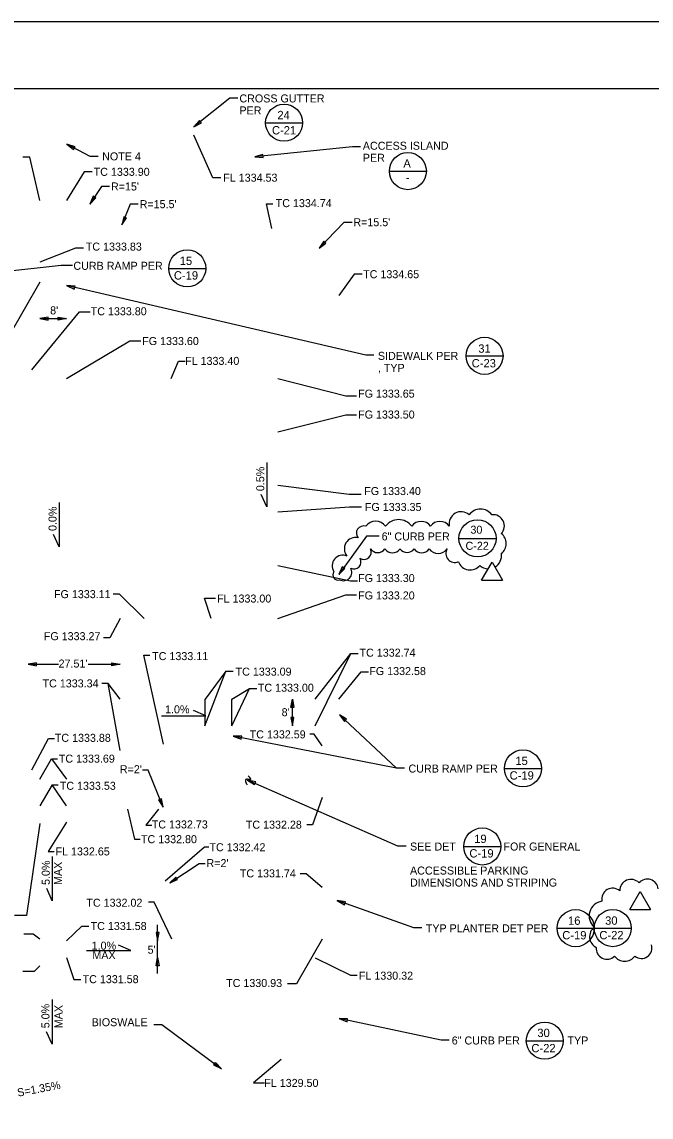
# Model space of a CAD drawing. Extents: x 0 to 3.5, y 0 to 3.39.
# Drawn here: x 1.981 to 2.766, y 1.132 to 2.5 of the extents above; entities that cross this region are included whole.
import ezdxf

# ---------------------------------------------------------------- set-up
doc = ezdxf.new("R2010")
doc.units = 0
for name, color, linetype in [('C-MARK', 7, 'Continuous'), ('C-MATC', 7, 'Continuous'), ('C-REVC', 7, 'Continuous'), ('C-TEXT', 7, 'Continuous'), ('G-TTLB-OTLN', 7, 'Continuous'), ('G-TTLB-VIEW', 7, 'Continuous')]:
    doc.layers.add(name, color=color, linetype=linetype)

msp = doc.modelspace()

# ---------------------------------------------------------------- linework, layer by layer
at = {"layer": 'C-MARK'}
for p, q in [((2.0031, 2.1293), (2.0364, 2.1293)), ((2.2863, 1.9495), (2.2863, 1.8941)), ((2.2863, 1.8941), (2.2794, 1.9095)), ((2.027, 1.8998), (2.027, 1.8444)), ((2.027, 1.8444), (2.0201, 1.8598)), ((1.9885, 1.6976), (2.0264, 1.6976)), ((2.0635, 1.6976), (2.1031, 1.6976)), ((2.2353, 1.6887), (2.2093, 1.654)), ((2.2427, 1.654), (2.2647, 1.6673)), ((2.2093, 1.6207), (2.2093, 1.654)), ((2.2427, 1.6207), (2.2427, 1.654)), ((2.3182, 1.6207), (2.3182, 1.654)), ((2.1547, 1.6329), (2.2101, 1.6329)), ((2.2101, 1.6329), (2.1947, 1.6398)), ((2.0175, 1.5793), (2.0364, 1.554)), ((2.0182, 1.5469), (2.0031, 1.5207)), ((2.0185, 1.4575), (2.0185, 1.4021)), ((2.0185, 1.4021), (2.0116, 1.4175)), ((2.1499, 1.352), (2.1499, 1.372)), ((1.9948, 1.3605), (1.9832, 1.3605)), ((2.0031, 1.354), (1.9948, 1.3605)), ((2.1166, 1.3399), (2.1012, 1.3467)), ((2.1499, 1.3311), (2.1499, 1.352)), ((2.0612, 1.3399), (2.1166, 1.3399)), ((2.1499, 1.3111), (2.1499, 1.3311)), ((1.9961, 1.3138), (1.9818, 1.3138)), ((2.0031, 1.3207), (1.9961, 1.3138)), ((2.0182, 1.2785), (2.0182, 1.2231)), ((2.0182, 1.2231), (2.0113, 1.2385))]:
    msp.add_line(p, q, dxfattribs=at)
for points in [[(2.2501, 2.4046), (2.2401, 2.4046), (2.1953, 2.3688)], [(2.2288, 2.305), (2.2188, 2.305), (2.1953, 2.3583)], [(2.0758, 2.332), (2.0658, 2.332), (2.0368, 2.3471)], [(2.4031, 2.3441), (2.3931, 2.3441), (2.2713, 2.3313)], [(2.0031, 2.277), (1.9907, 2.3312), (1.9819, 2.3312)], [(2.0682, 2.3128), (2.0582, 2.3128), (2.0364, 2.277)], [(2.0898, 2.2942), (2.0798, 2.2942), (2.0654, 2.2725)], [(2.1258, 2.2721), (2.1158, 2.2721), (2.1055, 2.2463)], [(2.2927, 2.2417), (2.2857, 2.2728), (2.2938, 2.2728)], [(2.3926, 2.2494), (2.3826, 2.2494), (2.3516, 2.2173)], [(2.0574, 2.2172), (2.0474, 2.2172), (2.0031, 2.2)], [(2.0439, 2.1956), (2.0296, 2.1956), (1.9542, 2.1875)], [(2.4051, 2.1847), (2.3951, 2.1847), (2.376, 2.1583)], [(2.0031, 2.175), (1.964, 2.1066), (1.955, 2.1066)], [(2.42, 2.0835), (2.41, 2.0835), (2.0364, 2.1707)], [(1.993, 2.0653), (2.0525, 2.1379), (2.066, 2.1379)], [(2.0364, 2.0545), (2.1155, 2.1014), (2.129, 2.1014)], [(2.1668, 2.0545), (2.1762, 2.0763), (2.1845, 2.0763)], [(2.3001, 2.0545), (2.3847, 2.0327), (2.3982, 2.0327)], [(2.3001, 1.9878), (2.3847, 2.0091), (2.3982, 2.0091)], [(2.3001, 1.9211), (2.3891, 1.9101), (2.4039, 1.9101)], [(2.3001, 1.8878), (2.3896, 1.8942), (2.4043, 1.8942)], [(2.4265, 1.8574), (2.4105, 1.8575), (2.376, 1.8097)], [(2.3001, 1.8211), (2.3907, 1.8019), (2.3994, 1.8019)], [(2.1332, 1.7547), (2.1023, 1.7849), (2.0947, 1.7849)], [(2.2168, 1.7545), (2.2087, 1.7802), (2.2222, 1.7802)], [(2.3001, 1.7545), (2.3847, 1.7841), (2.3982, 1.7841)], [(2.1031, 1.7545), (2.0902, 1.7305), (2.0826, 1.7305)], [(2.3468, 1.6207), (2.3912, 1.7111), (2.4003, 1.7111)], [(2.3468, 1.654), (2.3912, 1.7111), (2.4003, 1.7111)], [(2.1572, 1.5978), (2.1327, 1.709), (2.1402, 1.709)], [(2.2091, 1.6207), (2.2353, 1.6887), (2.2444, 1.6887)], [(2.376, 1.654), (2.4039, 1.6881), (2.4131, 1.6881)], [(2.1031, 1.5899), (2.0881, 1.6735), (2.0805, 1.6735)], [(2.1031, 1.654), (2.0881, 1.6735), (2.0805, 1.6735)], [(2.2427, 1.6207), (2.2647, 1.6673), (2.2738, 1.6673)], [(2.4582, 1.5679), (2.4482, 1.5679), (2.3771, 1.6345)], [(1.993, 1.5656), (2.0139, 1.6046), (2.0215, 1.6046)], [(2.4582, 1.5679), (2.4482, 1.5679), (2.2445, 1.6078)], [(2.3552, 1.5957), (2.3455, 1.6101), (2.3398, 1.6101)], [(2.0031, 1.554), (2.0175, 1.5793), (2.025, 1.5793)], [(2.1569, 1.519), (2.1384, 1.5654), (2.1312, 1.5654)], [(2.0364, 1.5207), (2.0182, 1.5469), (2.0258, 1.5469)], [(2.46, 1.4704), (2.45, 1.4704), (2.2621, 1.5529)], [(2.3552, 1.5311), (2.3435, 1.4969), (2.3364, 1.4969)], [(2.1124, 1.5165), (2.1212, 1.4792), (2.1284, 1.4792)], [(2.151, 1.5165), (2.1355, 1.4966), (2.1426, 1.4966)], [(2.0032, 1.4987), (1.9862, 1.3836), (1.9714, 1.3836)], [(2.0364, 1.5002), (2.0133, 1.4634), (2.0209, 1.4634)], [(2.1593, 1.4268), (2.2086, 1.4695), (2.214, 1.4695)], [(2.1652, 1.4244), (2.202, 1.4488), (2.2092, 1.4488)], [(2.3552, 1.4187), (2.3352, 1.4358), (2.328, 1.4358)], [(2.1677, 1.354), (2.1458, 1.4004), (2.1386, 1.4004)], [(2.4798, 1.3683), (2.4698, 1.3683), (2.3739, 1.4023)], [(2.0364, 1.352), (2.0556, 1.3705), (2.064, 1.3705)], [(2.3552, 1.354), (2.3233, 1.2983), (2.3121, 1.2983)], [(2.0364, 1.3311), (2.0455, 1.3038), (2.054, 1.3038)], [(2.3467, 1.3307), (2.3907, 1.309), (2.3992, 1.309)], [(2.1453, 1.2476), (2.1553, 1.2476), (2.2298, 1.1922)], [(2.5138, 1.2277), (2.5038, 1.2277), (2.3765, 1.2548)], [(2.3041, 1.2039), (2.2697, 1.1747), (2.2833, 1.1747)]]:
    msp.add_lwpolyline(points, dxfattribs=at)
msp.add_open_spline([(2.263, 1.558), (2.2689, 1.5523), (2.2569, 1.555), (2.2617, 1.5469)], degree=2, dxfattribs=at)
at = {"layer": 'C-MATC'}
msp.add_line((0.6372, 2.4167), (2.713, 2.4167), dxfattribs=at)
at = {"layer": 'C-REVC'}
for centre, radius, start, end in [((2.553, 1.8736), 0.0178, 36.8699, 143.1301), ((2.4222, 1.8608), 0.0154, 36.8699, 143.1301), ((2.4508, 1.8578), 0.0204, 36.8699, 143.1301), ((2.4789, 1.8613), 0.0147, 36.8699, 143.1301), ((2.5023, 1.8613), 0.0147, 36.8699, 143.1301), ((2.5288, 1.873), 0.0151, 48.7253, 191.1819), ((2.5688, 1.8704), 0.014, 316.581, 96.5491), ((2.4073, 1.8612), 0.00921, 74.4697, 218.909), ((2.5695, 1.8483), 0.0157, 306.8699, 53.1301), ((2.397, 1.8418), 0.014, 76.8763, 220.2645), ((2.3811, 1.8205), 0.0133, 66.89, 213.7391), ((2.4075, 1.8376), 0.00911, 238.444, 25.7343), ((2.4247, 1.8483), 0.0113, 216.8699, 323.1301), ((2.4431, 1.8486), 0.0118, 216.8699, 323.1301), ((2.4613, 1.8482), 0.011, 216.8699, 323.1301), ((2.4795, 1.8486), 0.0118, 216.8699, 323.1301), ((2.5002, 1.8501), 0.0141, 216.8699, 323.1301), ((2.5208, 1.8357), 0.011, 147.4131, 294.5304), ((2.563, 1.8331), 0.0162, 300.2363, 9.4597), ((2.3951, 1.8255), 0.00879, 242.2766, 29.7336), ((2.5401, 1.8309), 0.0156, 199.7229, 320.7723), ((2.563, 1.8331), 0.0162, 227.8866, 267.9338), ((2.3751, 1.8092), 0.00645, 142.6171, 288.0053), ((2.3819, 1.8124), 0.0105, 242.9766, 30.3928), ((2.7408, 1.4148), 0.014, 44.4945, 181.1728), ((2.7611, 1.4153), 0.0138, 6.9456, 138.0032), ((2.7179, 1.4042), 0.0136, 48.9741, 191.6731), ((2.7072, 1.383), 0.0187, 98.3653, 228.3728), ((2.7041, 1.3572), 0.015, 128.1326, 243.2886), ((2.7108, 1.3425), 0.0135, 174.6579, 313.9222), ((2.7538, 1.3432), 0.0132, 232.1847, 17.3271), ((2.7329, 1.3425), 0.016, 216.8699, 323.1301)]:
    msp.add_arc(centre, radius, start, end, dxfattribs=at)
at = {"layer": 'C-TEXT'}
for p, q in [((2.2846, 2.3739), (2.3309, 2.3739)), ((2.439, 2.3136), (2.4853, 2.3136)), ((2.1637, 2.192), (2.21, 2.192)), ((2.5347, 2.0827), (2.581, 2.0827)), ((2.526, 1.8548), (2.5724, 1.8548)), ((2.5544, 1.8026), (2.5675, 1.8252)), ((2.5675, 1.8252), (2.5805, 1.8026)), ((2.5544, 1.8026), (2.5805, 1.8026)), ((2.5544, 1.8026), (2.5544, 1.8026)), ((2.5805, 1.8026), (2.5805, 1.8026)), ((2.5827, 1.5673), (2.629, 1.5673)), ((2.5319, 1.4698), (2.5782, 1.4698)), ((2.7392, 1.391), (2.7523, 1.4136)), ((2.7523, 1.4136), (2.7653, 1.391)), ((2.7392, 1.391), (2.7653, 1.391)), ((2.7392, 1.391), (2.7392, 1.391)), ((2.7653, 1.391), (2.7653, 1.391)), ((2.6484, 1.3677), (2.6947, 1.3677)), ((2.6947, 1.3678), (2.741, 1.3678)), ((2.6099, 1.2271), (2.6562, 1.2271))]:
    msp.add_line(p, q, dxfattribs=at)
for points in [[(2.2023, 2.3767), (2.1953, 2.3688), (2.2046, 2.3738)], [(2.0469, 2.3439), (2.0368, 2.3471), (2.0452, 2.3406)], [(2.2815, 2.3342), (2.2713, 2.3313), (2.2818, 2.3305)], [(2.0696, 2.2822), (2.0654, 2.2725), (2.0727, 2.2801)], [(2.1077, 2.2566), (2.1055, 2.2463), (2.1111, 2.2553)], [(2.3575, 2.226), (2.3516, 2.2173), (2.3601, 2.2235)], [(2.0469, 2.1697), (2.0364, 2.1707), (2.046, 2.1662)], [(2.0135, 2.1311), (2.0031, 2.1293), (2.0135, 2.1275)], [(2.026, 2.1311), (2.0364, 2.1293), (2.026, 2.1275)], [(2.3805, 1.8194), (2.376, 1.8098), (2.3835, 1.8173)], [(1.9989, 1.6994), (1.9885, 1.6976), (1.9989, 1.6957)], [(2.0927, 1.6994), (2.1031, 1.6976), (2.0927, 1.6957)], [(2.3164, 1.6436), (2.3182, 1.654), (2.3201, 1.6436)], [(2.3164, 1.6311), (2.3182, 1.6207), (2.3201, 1.6311)], [(2.3859, 1.6288), (2.3771, 1.6345), (2.3834, 1.6261)], [(2.255, 1.6076), (2.2445, 1.6078), (2.2543, 1.604)], [(2.2725, 1.5506), (2.2621, 1.5529), (2.271, 1.5473)], [(2.1513, 1.528), (2.1569, 1.519), (2.1547, 1.5293)], [(2.1729, 1.4317), (2.1652, 1.4244), (2.1749, 1.4286)], [(2.3843, 1.4006), (2.3739, 1.4023), (2.3831, 1.3971)], [(2.1481, 1.3624), (2.1499, 1.352), (2.1518, 1.3624)], [(2.1481, 1.3207), (2.1499, 1.3311), (2.1518, 1.3207)], [(2.3871, 1.2545), (2.3765, 1.2548), (2.3864, 1.2509)], [(2.2224, 1.1998), (2.2298, 1.1922), (2.2202, 1.1968)]]:
    msp.add_lwpolyline(points, close=True, dxfattribs=at)
msp.add_circle((2.5492, 1.8548), 0.0232, dxfattribs=at)
for centre in [(2.3078, 2.374), (2.4623, 2.3136), (2.187, 2.1921), (2.558, 2.0828), (2.606, 1.5674), (2.5552, 1.4699), (2.6717, 1.3678), (2.718, 1.3679), (2.6332, 1.2272)]:
    msp.add_ellipse(centre, major_axis=(0, 0.0232), ratio=0.994695, dxfattribs=at)
at = {"layer": 'G-TTLB-OTLN'}
msp.add_lwpolyline([(0, 0), (3.5, 0), (3.5, 2.5), (0, 2.5)], close=True, dxfattribs=at)
at = {"layer": 'G-TTLB-VIEW'}
msp.add_lwpolyline([(0.1667, 2.4167), (3.0729, 2.4167), (3.0729, 0.0833), (0.1667, 0.0833)], close=True, dxfattribs=at)

# ---------------------------------------------------------------- texts
at = {"layer": 'C-TEXT'}
for s, height, rotation, p in [('CROSS GUTTER', 0.01, 360, (2.2521, 2.3994)), ('PER', 0.01, 360, (2.2521, 2.3844)), ('24', 0.01042, 360, (2.2995, 2.3784)), ('C-21', 0.01042, 360, (2.2927, 2.3594)), ('ACCESS ISLAND', 0.01, 360, (2.4061, 2.3403)), ('PER', 0.01, 360, (2.4061, 2.3253)), ('A', 0.0104, 360, (2.4567, 2.318)), ('-', 0.0104, 360, (2.4597, 2.3004)), ('15', 0.01042, 360, (2.1776, 2.1963)), ('CURB RAMP PER', 0.01, 360, (2.0449, 2.1903)), ('C-19', 0.01042, 360, (2.1703, 2.1781)), ('31', 0.01042, 360, (2.5502, 2.0867)), ('SIDEWALK PER', 0.01, 360, (2.4249, 2.0778)), (', TYP', 0.01, 360, (2.4249, 2.0628)), ('C-23', 0.01042, 360, (2.542, 2.0684)), ('0.5%', 0.01, 90, (2.2831, 1.9138)), ('0.0%', 0.01, 90, (2.0239, 1.864)), ('15', 0.01042, 360, (2.5965, 1.5716)), ('CURB RAMP PER', 0.01, 360, (2.4631, 1.5622)), ('C-19', 0.01042, 360, (2.5893, 1.5534)), ('19', 0.01042, 360, (2.5451, 1.4742)), ('SEE DET                FOR GENERAL', 0.01, 360, (2.465, 1.4648)), ('C-19', 0.01042, 360, (2.5391, 1.4561)), ('5.0%', 0.01, 90, (2.0154, 1.4218)), ('MAX', 0.01, 90, (2.0307, 1.4218)), ('ACCESSIBLE PARKING', 0.01, 360, (2.465, 1.4348)), ('DIMENSIONS AND STRIPING', 0.01, 360, (2.465, 1.4198)), ('16', 0.01042, 360, (2.6622, 1.372)), ('30', 0.01042, 360, (2.7085, 1.3721)), ('TYP PLANTER DET PER', 0.01, 360, (2.4847, 1.3626)), ('C-19', 0.01042, 360, (2.655, 1.3538)), ('C-22', 0.01042, 360, (2.7013, 1.3539)), ('5.0%', 0.01, 90, (2.015, 1.2428)), ('MAX', 0.01, 90, (2.0313, 1.2428)), ('6" CURB PER              , TYP', 0.01, 360, (2.5171, 1.2225)), ('30', 0.01042, 360, (2.6239, 1.2318)), ('C-22', 0.01042, 360, (2.6165, 1.2127)), (' S=1.35%', 0.01, 10.4915, (1.9721, 1.1566))]:
    msp.add_text(s, height=height, rotation=rotation, dxfattribs=at).set_placement(p)
for s, p in [('NOTE 4', (2.0808, 2.327)), ('TC 1333.90', (2.0702, 2.3077)), ("R=15'", (2.0918, 2.2894)), ('FL 1334.53', (2.2319, 2.3004)), ("R=15.5'", (2.1276, 2.2673)), ('TC 1334.74', (2.2974, 2.2686)), ("R=15.5'", (2.3943, 2.2448)), ('TC 1333.83', (2.0604, 2.2143)), ('TC 1334.65', (2.4065, 2.1798)), ("8'", (2.0159, 2.1346)), ('TC 1333.80', (2.0665, 2.1335)), ('FG 1333.60', (2.1308, 2.0963)), ('FL 1333.40', (2.1843, 2.0715)), ('FG 1333.65', (2.4002, 2.0306)), ('FG 1333.50', (2.4002, 2.0045)), ('FG 1333.40', (2.4079, 1.9089)), ('FG 1333.35', (2.4087, 1.889)), ('6" CURB PER', (2.4296, 1.8522)), ('30', (2.5404, 1.8606)), ('C-22', (2.5343, 1.8405)), ('FG 1333.30', (2.4002, 1.8002)), ('FG 1333.11', (2.0207, 1.7801)), ('FL 1333.00', (2.2242, 1.7746)), ('FG 1333.20', (2.4002, 1.7785)), ('FG 1333.27', (2.008, 1.7276)), ('TC 1333.11', (2.1432, 1.7027)), ('TC 1332.74', (2.402, 1.707)), ("27.51'", (2.0264, 1.6934)), ('TC 1333.09', (2.2473, 1.6833)), ('FG 1332.58', (2.4142, 1.684)), ('TC 1333.34', (2.0064, 1.6686)), ('TC 1333.00', (2.2751, 1.6632)), ('1.0%', (2.1593, 1.6362)), ("8'", (2.3048, 1.6326)), ('TC 1332.59', (2.2649, 1.6049)), ('TC 1333.88', (2.0217, 1.6006)), ('TC 1333.69', (2.0267, 1.5746)), ("R=2'", (2.1029, 1.5614)), ('TC 1333.53', (2.0279, 1.5407)), ('TC 1332.73', (2.1427, 1.4924)), ('TC 1332.28', (2.2601, 1.4921)), ('TC 1332.80', (2.1292, 1.474)), ('FL 1332.65', (2.0226, 1.4587)), ('TC 1332.42', (2.2147, 1.4639)), ("R=2'", (2.211, 1.4441)), ('TC 1331.74', (2.2526, 1.4313)), ('TC 1332.02', (2.0611, 1.3946)), ('TC 1331.58', (2.0664, 1.3655)), ('1.0%', (2.0677, 1.341)), ("5'", (2.1375, 1.3359)), ('MAX', (2.0686, 1.3291)), ('FL 1330.32', (2.4012, 1.3035)), ('TC 1331.58', (2.0564, 1.2991)), ('TC 1330.93', (2.2355, 1.2943)), ('BIOSWALE', (2.0677, 1.2453)), ('FL 1329.50', (2.2831, 1.1695))]:
    msp.add_text(s, height=0.01, dxfattribs=at).set_placement(p)

doc.saveas('drawing.dxf')
